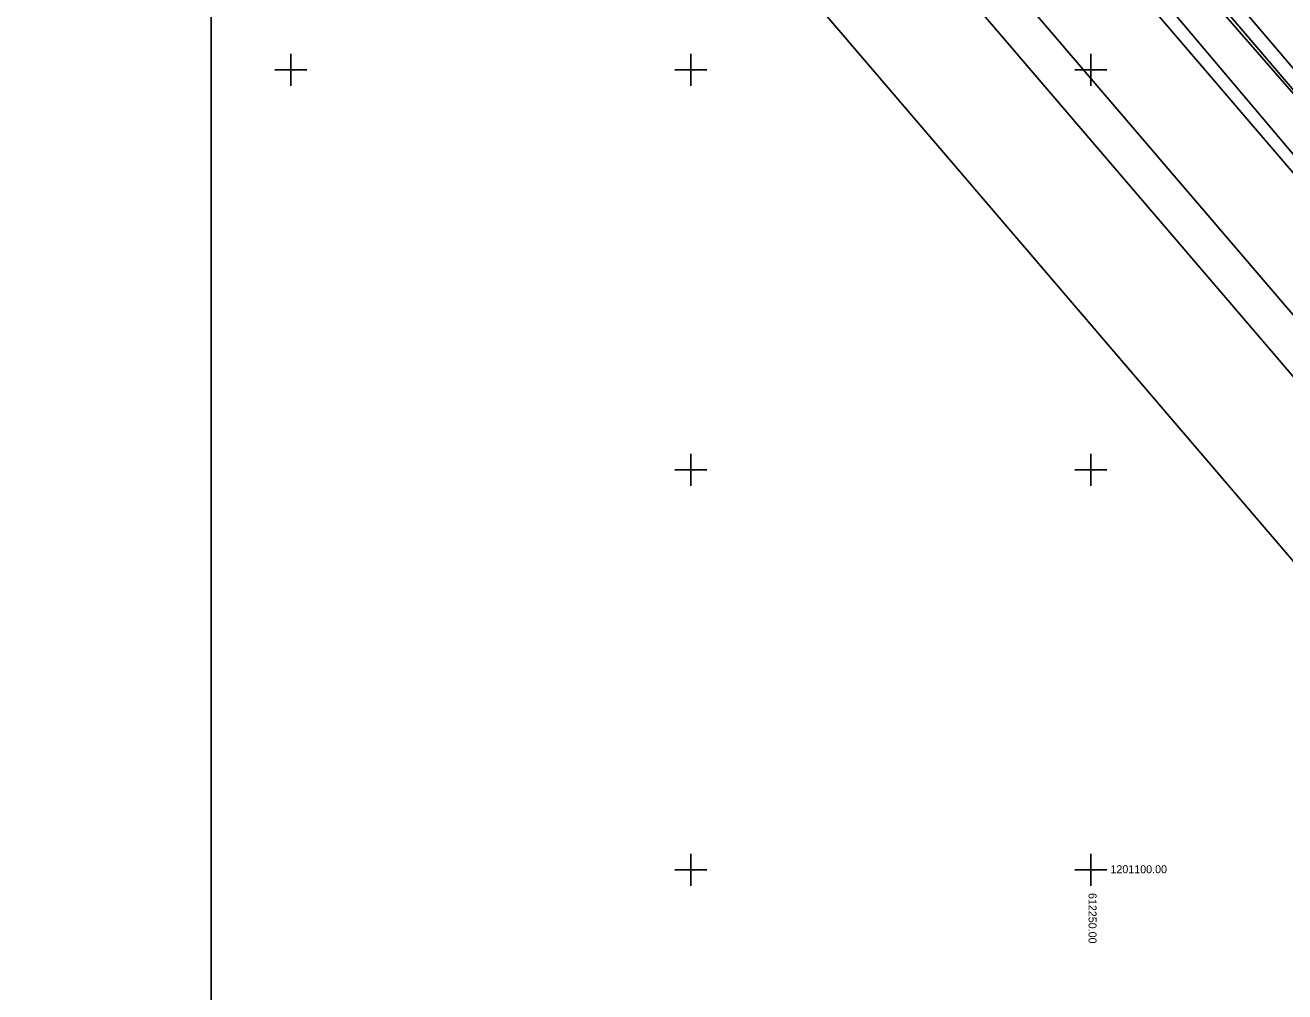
# Model space of a CAD drawing. Extents: x -612546 to -611926, y -1201932 to -1200444.
# Drawn here: x -612383.2 to -612225.8, y -1201115.3 to -1200994.4 of the extents above; entities that cross this region are included whole.
import ezdxf

# ---------------------------------------------------------------- set-up
doc = ezdxf.new("R2010")
doc.units = 0
for name, color, linetype in [('14 hrana pata svahu', 7, 'Continuous'), ('61 legenda křížky', 7, 'Continuous'), ('Hranice parcel', 7, 'Continuous'), ('Vnitřní kresba', 7, 'Continuous'), ('Vrstva 63', 7, 'Continuous')]:
    doc.layers.add(name, color=color, linetype=linetype)

msp = doc.modelspace()

# ---------------------------------------------------------------- linework, layer by layer
at = {"layer": '14 hrana pata svahu'}
msp.add_lwpolyline([(-612083.4, -1201170.96), (-612107.88, -1201140.83), (-612125.72, -1201119.76), (-612151.16, -1201088.66), (-612173.22, -1201063.29), (-612197.5, -1201034.61), (-612222.4, -1201005.63), (-612247.09, -1200977.25), (-612284.99, -1200933.95), (-612307.37, -1200907.39), (-612317.17, -1200894.63), (-612323.51, -1200877.98), (-612336.33, -1200841.94)], dxfattribs=at)
at = {"layer": '61 legenda křížky'}
for p, q in [((-612350, -1201002), (-612350, -1200998)), ((-612300, -1201002), (-612300, -1200998)), ((-612250, -1201002), (-612250, -1200998)), ((-612352, -1201000), (-612348, -1201000)), ((-612302, -1201000), (-612298, -1201000)), ((-612252, -1201000), (-612248, -1201000)), ((-612300, -1201052), (-612300, -1201048)), ((-612250, -1201052), (-612250, -1201048)), ((-612302, -1201050), (-612298, -1201050)), ((-612252, -1201050), (-612248, -1201050)), ((-612300, -1201102), (-612300, -1201098)), ((-612250, -1201102), (-612250, -1201098)), ((-612302, -1201100), (-612298, -1201100)), ((-612252, -1201100), (-612248, -1201100))]:
    msp.add_line(p, q, dxfattribs=at)
at = {"layer": 'Hranice parcel'}
for points in [[(-612492.54, -1200475.45), (-612489.15, -1200479.9), (-612487.29, -1200482.34), (-612470.55, -1200499.86), (-612454.58, -1200517.89), (-612449.12, -1200526.98), (-612444.88, -1200537.01), (-612400.71, -1200658.68), (-612382.76, -1200708.97), (-612320.94, -1200880.21), (-612316.28, -1200891.06), (-612307.37, -1200903.62), (-612259.67, -1200958.71), (-612214.29, -1201012.03), (-612172.62, -1201060.98), (-612120.7, -1201123.05), (-612073.85, -1201178.4), (-612068.4, -1201184.83), (-612055.42, -1201199.11), (-612044.78, -1201213.9), (-612040.42, -1201224.33), (-612036.87, -1201232.26)], [(-612053.63, -1201234.04), (-612049.72, -1201229.74), (-612051.31, -1201220.57), (-612058.28, -1201208.42), (-612073.89, -1201189.58), (-612079.31, -1201183.16), (-612173.25, -1201072.99), (-612266.53, -1200963.98), (-612308.11, -1200916.05), (-612320.05, -1200901.46), (-612326.37, -1200888.91), (-612352.76, -1200817.26), (-612383.45, -1200732.24), (-612424.46, -1200618.96), (-612450.75, -1200547.77), (-612455.75, -1200534.91), (-612462.05, -1200524.68), (-612490.01, -1200492.58), (-612497.19, -1200482.99)], [(-612504.85, -1200495.41), (-612492.66, -1200506.93), (-612476.27, -1200525), (-612462.43, -1200549.41), (-612435.01, -1200623.69), (-612394.62, -1200736.44), (-612362.83, -1200822.52), (-612336.91, -1200893.7), (-612329.46, -1200906.86), (-612317.29, -1200922.46), (-612274.72, -1200972.15), (-612181.97, -1201080.59), (-612092.56, -1201185.28), (-612096.16, -1201188.77)], [(-612098.55, -1201185.97), (-612185.77, -1201083.84), (-612278.52, -1200975.4), (-612321.16, -1200925.63), (-612333.63, -1200909.64), (-612341.47, -1200895.8), (-612367.52, -1200824.24), (-612399.32, -1200738.15), (-612439.71, -1200625.4), (-612466.98, -1200551.52), (-612480.35, -1200527.95), (-612496.23, -1200510.43), (-612507.54, -1200499.75)], [(-612480.63, -1200557.86), (-612453.81, -1200630.53), (-612413.42, -1200743.28), (-612381.61, -1200829.41), (-612355.13, -1200902.11), (-612346.14, -1200918), (-612332.78, -1200935.12), (-612289.91, -1200985.15), (-612197.17, -1201093.58), (-612109.96, -1201195.71)]]:
    msp.add_lwpolyline(points, dxfattribs=at)
at = {"layer": 'Vnitřní kresba'}
msp.add_line((-612303.02, -1200910.37), (-612174.91, -1201061.11), dxfattribs=at)
msp.add_lwpolyline([(-612077.99, -1201182.01), (-612172.2, -1201072.72), (-612264.55, -1200963.36), (-612306.48, -1200914.97), (-612319.15, -1200900.26), (-612324.5, -1200887.86), (-612350.35, -1200818.69), (-612381.6, -1200731.97), (-612422.84, -1200618.87), (-612449.81, -1200544.11), (-612465.28, -1200517.45), (-612482.79, -1200495.64), (-612497.19, -1200482.99)], dxfattribs=at)
at = {"layer": 'Vrstva 63'}
msp.add_line((-612359.93, -1201251.26), (-612359.93, -1200831.26), dxfattribs=at)

# ---------------------------------------------------------------- texts
at = {"layer": '61 legenda křížky'}
msp.add_text('1201100.00', height=1, dxfattribs=at).set_placement((-612247.55, -1201100.43))
msp.add_text('612250.00', height=1, rotation=270, dxfattribs=at).set_placement((-612250.29, -1201102.9))

doc.saveas('drawing.dxf')
